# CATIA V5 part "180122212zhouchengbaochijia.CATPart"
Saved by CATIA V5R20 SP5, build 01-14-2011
Part number: Part2
Bounding box of the stored display mesh (mm): x -100 to 100, y -99.999 to 99.999, z -2.5 to 19.843
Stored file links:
  E:\180122212zhouchengbaochijia.CATPart
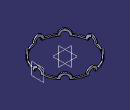
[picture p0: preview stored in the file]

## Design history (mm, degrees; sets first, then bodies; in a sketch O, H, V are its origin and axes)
Body1 (main body)
  Sketch1 on xy-plane, origin (0, 0, 0), H (1, 0, 0), V (0, 1, 0)
    circle A1 centre (0, 0) radius 100
  Pad1: profile Sketch1, direction (0, 0, 1), length 2.5, mirrored extent, thin wall 5
  Body2
    Sketch2 on xy-plane, origin (0, 0, 0), H (1, 0, 0), V (0, 1, 0)
      arc A1 centre (97.5, 0) radius 20 from (97.5, -20) to (97.5, 20) ccw
      point P1 (97.5, 0)
      point P2 (117.5, 0)
      axis line L1 (97.5, 50) -> (97.5, -40)
      point P5 (97.5, 20)
      point P6 (97.5, -20)
      distance V L1 = 97.5
      radius A1 = 20
      coincidence: P1 H, A1 P2, P2 H, L1 P5, L1 P6, P1 L1
      vertical: L1 V
    Shaft1: profile Sketch2, axis Sketch2.L1, angle 360
    CircPattern1: of Shaft1, instances 8, angular step 45, axis from end face of Pad1
    Sketch3 on xy-plane, origin (0, 0, 0), H (1, 0, 0), V (0, 1, 0)
      circle A1 centre (0, 0) radius 95
    Pocket1: profile Sketch3, direction (0, 0, -1), length 20, mirrored extent
    Split1: SplitPlane start face of Pad1
    Sketch4 on xy-plane, origin (0, 0, 0), H (1, 0, 0), V (0, 1, 0)
      circle A1 centre (0, 0) radius 100
      point P1 (100, 0)
      circle A2 centre (0, 0) radius 120
      coincidence: A1 P1, P1 H
    Pocket2: profile Sketch4, direction (0, 0, -1), length 20, mirrored extent
  Assemble1: tool Body2
  Body3
    Plane1: type Offset, RefPlane yz-plane, Offset 97.5
    Sketch5 on Plane1, origin (97.5, 0, 0), H (0, 1, 0), V (0, 0, 1)
      arc A1 centre (0, 0) radius 12 from (-12, 0) to (12, 0) ccw
    Shaft2: profile Sketch5, axis Sketch5.H, angle 360
    CircPattern2: of Shaft2, instances 8, angular step 45, axis from face of Pad1
  Remove1: tool Body3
